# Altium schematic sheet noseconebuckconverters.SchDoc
size A4
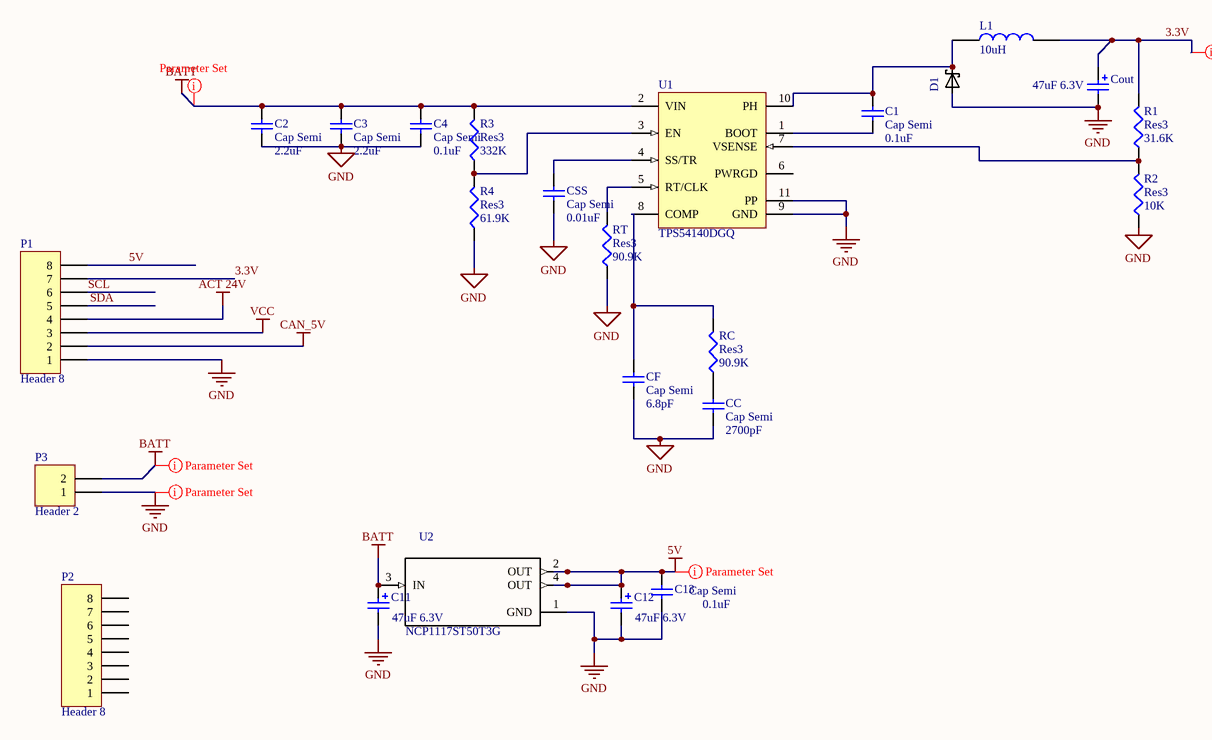
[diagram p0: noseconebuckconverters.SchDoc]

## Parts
C1  Cap Semi  value 0.1uF  [C1206]
C2  Cap Semi  value 2.2uF  [C1206]
C3  Cap Semi  value 2.2uF  [C1206]
C4  Cap Semi  value 0.1uF  [C1206]
C11  47uF 6.3V  [Panasonic Capacitor, ZA-Series, F-Size]
C12  47uF 6.3V  [Panasonic Capacitor, ZA-Series, F-Size]
C13  Cap Semi  value 0.1uF  [C1206]
CC  Cap Semi  value 2700pF  [C1206]
CF  Cap Semi  value 6.8pF  [C1206]
Cout  47uF 6.3V  [Panasonic Capacitor, ZA-Series, F-Size]
CSS  Cap Semi  value 0.01uF  [C1206]
D1  (no value)  [SMA-DIODE]
L1  10uH  [CDR7D28MNNP101NC]
P1  Header 8  [HDR1X8]
P2  Header 8  [HDR1X8]
P3  Header 2  [HDR1X2]
R1  Res3  value 31.6K  [J1-0603]
R2  Res3  value 10K  [J1-0603]
R3  Res3  value 332K  [J1-0603]
R4  Res3  value 61.9K  [J1-0603]
RC  Res3  value 90.9K  [J1-0603]
RT  Res3  value 90.9K  [J1-0603]
U1  TPS54140DGQ  [DGQ10-1675X1445TP_N]
U2  NCP1117ST50T3G  [SOT230P700X180-4N]

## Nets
5V: C12.1 C13.2 P1.8 U2.2(OUT) U2.4(OUT)
ACT 24V: P1.4
BATT: C2.2 C3.2 C4.2 C11.1 P3.2 R3.2 U1.2(VIN) U2.3(IN)
CAN_5V: P1.2
GND: C2.1 C3.1 C4.1 C11.2 C12.2 C13.1 CC.1 CF.1 Cout.2 CSS.1 D1.1(A) P1.1 P3.1 R2.1 R4.1 RT.1 U1.9(GND) U1.11(PP) U2.1(GND)
VCC: P1.3
3.3V: Cout.1 L1.2 P1.7 R1.2
SCL: P1.6
SDA: P1.5
NetC1_1: C1.1 U1.1(BOOT)
NetC1_2: C1.2 D1.2(C) L1.1 U1.10(PH)
NetCC_2: CC.2 RC.1
NetCF_2: CF.2 RC.2 U1.8(COMP)
NetCSS_2: CSS.2 U1.4(SS/TR)
NetR1_1: R1.1 R2.2 U1.7(VSENSE)
NetR3_1: R3.1 R4.2 U1.3(EN)
NetRT_2: RT.2 U1.5(RT/CLK)

Not connected (* = marked no-connect by the designer): P2 1 2 3 4 5 6 7 8; U1 6(PWRGD)

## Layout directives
rule Width Constraint [Pref Width = 0.4mm    Min Width = 0.4mm    Max Width = 0.4mm]: 3.3V, 5V, BATT, GND
rule Width Constraint [Pref Width = 0.3mm    Min Width = 0.3mm    Max Width = 0.3mm]: BATT

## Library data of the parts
C1-C4 C13 CC CF CSS = Cap Semi: Capacitor (Semiconductor SIM Model)
C11 C12 Cout = Panasonic 150uF 35V: EEHZA1V151V 150uF 35V Hyprid Cap Vibration-Proof
D1 = B220A-13-F: B220A Series 20 V 2 A Surface Mount Schottky Barrier Rectifier - SMA; MF: Diodes Inc.
L1 = CDR7D28MNNP-101NC: Fixed Inductors 100uH .65A; Manufacturer_Name: Sumida; Geometry.Height: 3mm
P1 P2 = Header 8: Header, 8-Pin
P3 = Header 2: Header, 2-Pin
R1-R4 RC RT = Res3: Resistor
U1 = TPS54140DGQ: Buck Inverting Buck-Boost Step Down Regulator with 3.5 to 42 V Input and 0.8 to 39 V Output, -40 to 150 degC, 10-Pin MSOP-PowerPAD (DGQ), Green (RoHS & no Sb/Br); Manufacturer: Texas Instruments; Duty Cycle(Max)(%): 98; Iout(Max)(A): 1.5; Iq(Typ)(mA): 0.116; Rating: Catalog; Regulated Outputs(#): 1; SubFamily: Step-Down Regulator; Switch Current Limit(Typ)(A): 1.8; Topology: Buck, Inverting Buck-Boost; Vin(Max)(V): 42; Vin(Min)(V): 3.5; Vout(Max)(V): 39; Vout(Min)(V): 0.8
U2 = NCP1117ST50T3G: MF: ON Semiconductor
